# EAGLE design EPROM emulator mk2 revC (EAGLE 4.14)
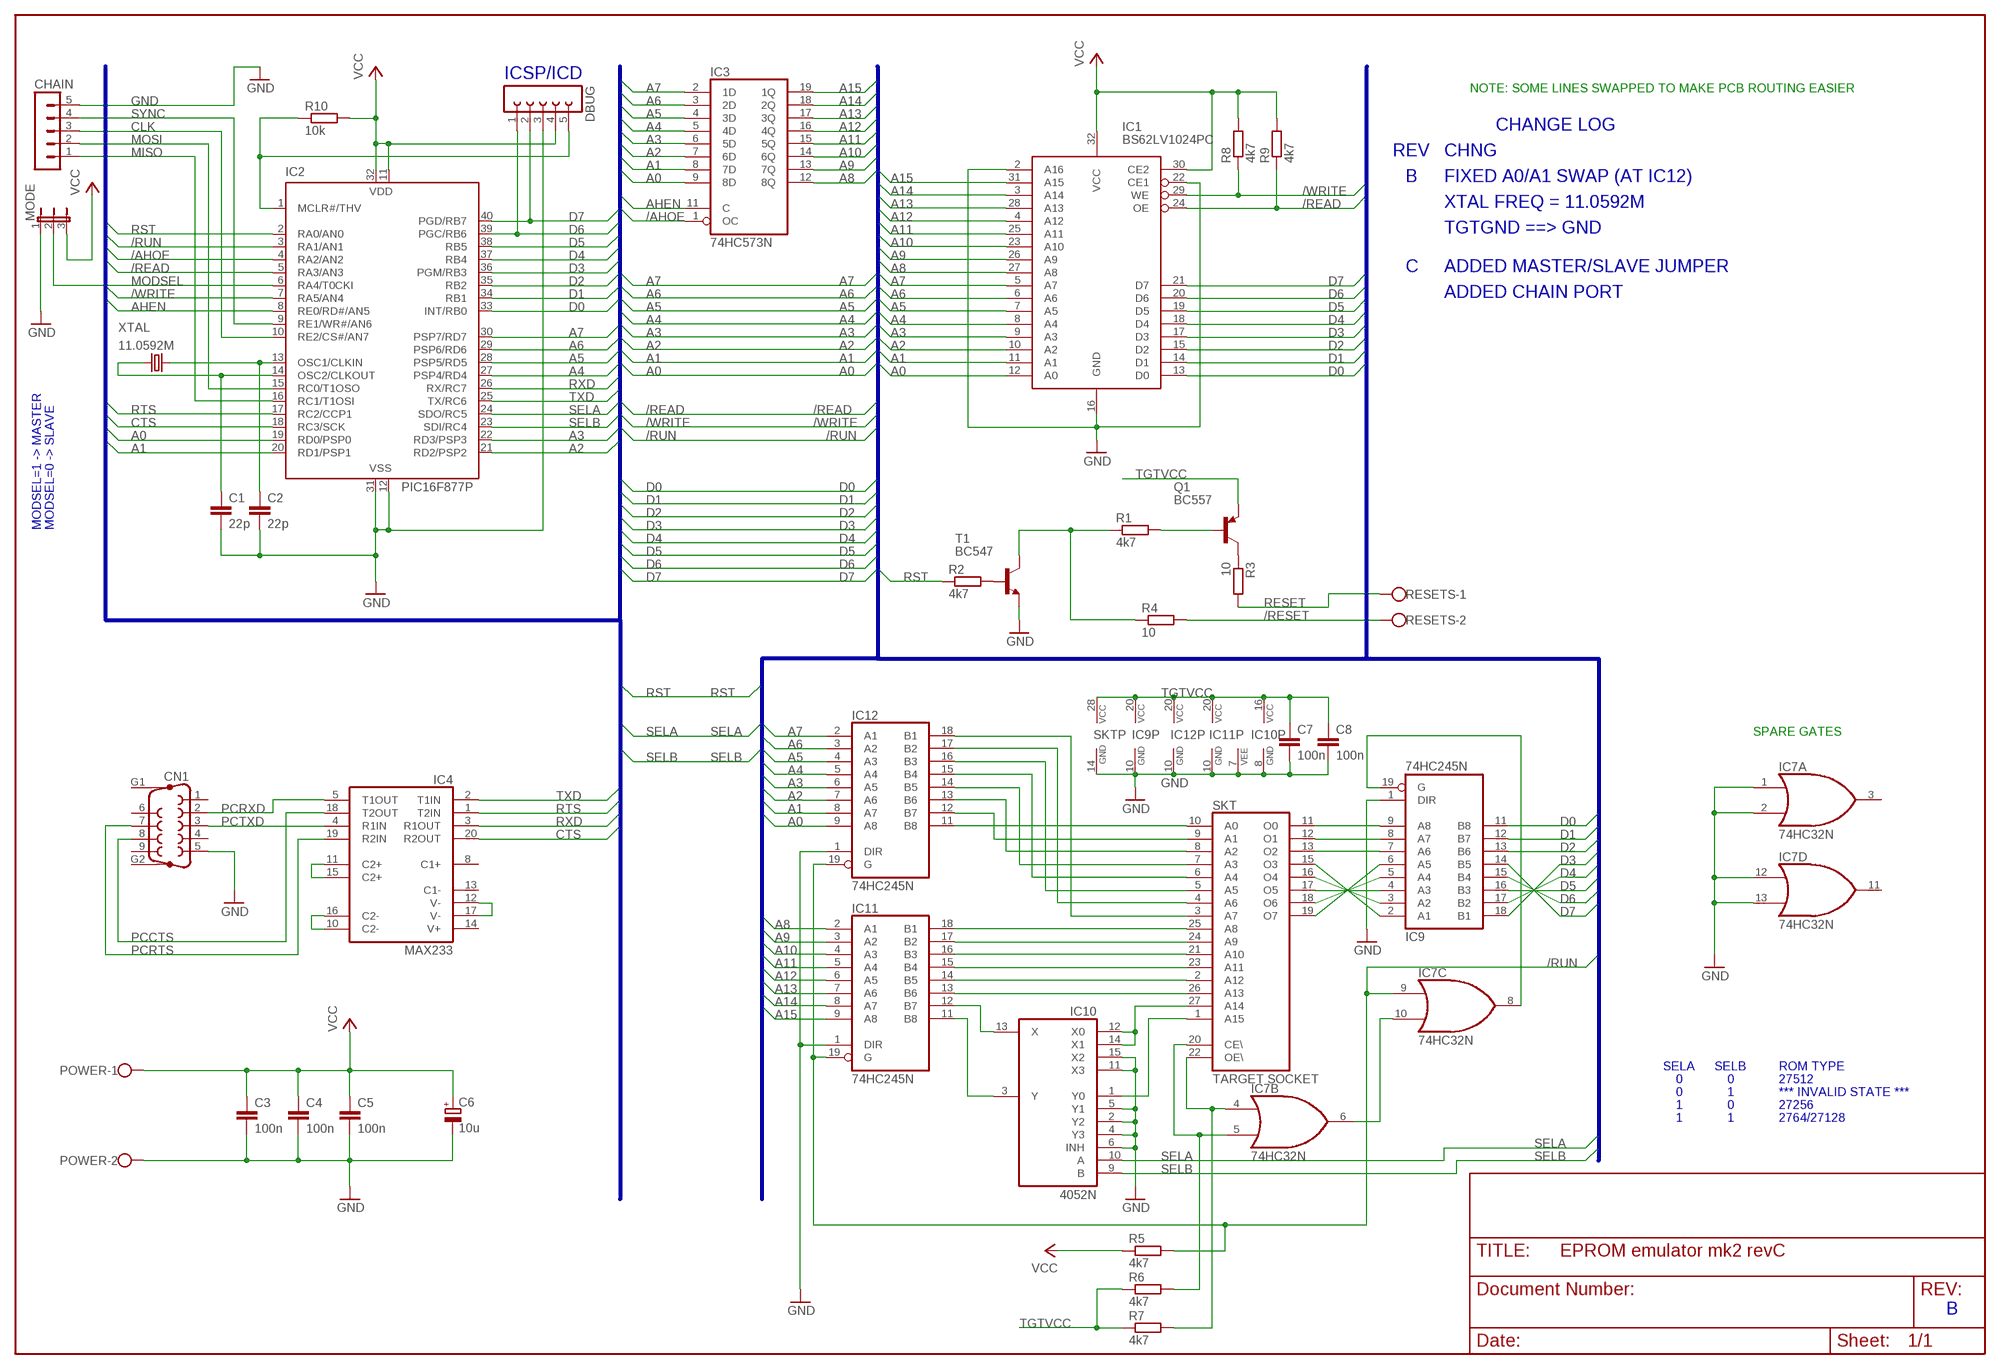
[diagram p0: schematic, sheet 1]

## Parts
C1  22p  C-EU025-024X044  [C025-024X044]
C2  22p  C-EU025-024X044  [C025-024X044]
C3  100n  C-EU050-025X075  [C050-025X075]
C4  100n  C-EU050-025X075  [C050-025X075]
C5  100n  C-EU050-025X075  [C050-025X075]
C6  10u  CPOL-EUE2.5-5  [E2,5-5]
C7  100n  C-EU050-025X075  [C050-025X075]
C8  100n  C-EU050-025X075  [C050-025X075]
CHAIN  MA05-1  [MA05-1]
CN1  F09HP  [F09HP]
DBUG  FE05-1  [FE05-1]
IC1  BS62LV1024PC  [DIL32]
IC2  PIC16F877P  [DIL40]
IC3  74HC573N  [DIL20]
IC4  MAX233  [DIL20]
IC7  74HC32N  74LS32N  [DIL14]
IC9  74HC245N  74HCT245N  [DIL20]
IC10  4052N  [DIL16]
IC11  74HC245N  74HCT245N  [DIL20]
IC12  74HC245N  74HCT245N  [DIL20]
MODE  JP2E  [JP2]
POWER  W237-02P  [W237-132]
Q1  BC557  [TO92]
R1  4k7  R-EU_0207/10  [0207/10]
R2  4k7  R-EU_0207/10  [0207/10]
R3  10  R-EU_0207/10  [0207/10]
R4  10  R-EU_0207/10  [0207/10]
R5  4k7  R-EU_0207/10  [0207/10]
R6  4k7  R-EU_0207/10  [0207/10]
R7  4k7  R-EU_0207/10  [0207/10]
R8  4k7  R-EU_0207/10  [0207/10]
R9  4k7  R-EU_0207/10  [0207/10]
R10  10k  R-EU_0207/10  [0207/10]
RESETS  W237-102  [W237-102]
SKT  TARGET SOCKET  27512  [DIL28]
T1  BC547  [TO92]
XTAL  11.0592M  CRYTALHC49U-V  [HC49U-V]

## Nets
/AHOE: IC2.4(RA2/AN2) IC3.1(OC)
/READ: IC1.24(OE) IC2.5(RA3/AN3) R9.1
/RESET: R4.2 RESETS.2
/RUN: IC2.3(RA1/AN1) IC7.9(C:I0) IC11.19(G) IC12.19(G) R5.2
/WRITE: IC1.29(WE) IC2.7(RA5/AN4) R8.1
A0: IC1.12(A0) IC2.19(RD0/PSP0) IC3.9(8D) IC12.9(A8)
A1: IC1.11(A1) IC2.20(RD1/PSP1) IC3.8(7D) IC12.8(A7)
A2: IC1.10(A2) IC2.21(RD2/PSP2) IC3.7(6D) IC12.7(A6)
A3: IC1.9(A3) IC2.22(RD3/PSP3) IC3.6(5D) IC12.6(A5)
A4: IC1.8(A4) IC2.27(PSP4/RD4) IC3.5(4D) IC12.5(A4)
A5: IC1.7(A5) IC2.28(PSP5/RD5) IC3.4(3D) IC12.4(A3)
A6: IC1.6(A6) IC2.29(PSP6/RD6) IC3.3(2D) IC12.3(A2)
A7: IC1.5(A7) IC2.30(PSP7/RD7) IC3.2(1D) IC12.2(A1)
A8: IC1.27(A8) IC3.12(8Q) IC11.2(A1)
A9: IC1.26(A9) IC3.13(7Q) IC11.3(A2)
A10: IC1.23(A10) IC3.14(6Q) IC11.4(A3)
A11: IC1.25(A11) IC3.15(5Q) IC11.5(A4)
A12: IC1.4(A12) IC3.16(4Q) IC11.6(A5)
A13: IC1.28(A13) IC3.17(3Q) IC11.7(A6)
A14: IC1.3(A14) IC3.18(2Q) IC11.8(A7)
A15: IC1.31(A15) IC3.19(1Q) IC11.9(A8)
AHEN: IC2.8(RE0/RD#/AN5) IC3.11(C)
CLK: CHAIN.3 IC2.10(RE2/CS#/AN7)
CTS: IC2.18(RC3/SCK) IC4.20(R2OUT)
D0: IC1.13(D0) IC2.33(INT/RB0) IC9.11(B8)
D1: IC1.14(D1) IC2.34(RB1) IC9.12(B7)
D2: IC1.15(D2) IC2.35(RB2) IC9.13(B6)
D3: IC1.17(D3) IC2.36(PGM/RB3) IC9.18(B1)
D4: IC1.18(D4) IC2.37(RB4) IC9.17(B2)
D5: IC1.19(D5) IC2.38(RB5) IC9.16(B3)
D6: DBUG.1 IC1.20(D6) IC2.39(PGC/RB6) IC9.15(B4)
D7: DBUG.2 IC1.21(D7) IC2.40(PGD/RB7) IC9.14(B5)
GND: C1.2 C2.2 C3.2 C4.2 C5.2 C6.- C7.2 C8.2 CHAIN.5 CN1.5 DBUG.3 IC1.2(A16) IC1.16(GND) IC1.22(CE1) IC2.12(VSS) IC2.31(VSS) IC7.1(A:I0) IC7.2(A:I1) IC7.12(D:I0) IC7.13(D:I1) IC9.1(DIR) IC9.10(GND) IC10.2(Y2) IC10.4(Y3) IC10.5(Y1) IC10.6(INH) IC10.7(VEE) IC10.8(GND) IC10.11(X3) IC10.15(X2) IC11.1(DIR) IC11.10(GND) IC12.1(DIR) IC12.10(GND) MODE.1 POWER.2 SKT.14(GND) T1.1(E)
MISO: CHAIN.1 IC2.16(RC1/T1OSI)
MODSEL: IC2.6(RA4/T0CKI) MODE.2
MOSI: CHAIN.2 IC2.15(RC0/T1OSO)
N$1: C2.1 IC2.13(OSC1/CLKIN) XTAL.2
N$2: C1.1 IC2.14(OSC2/CLKOUT) XTAL.1
N$3: DBUG.5 IC2.1(MCLR#/THV) R10.1
N$4: IC9.6(A5) SKT.19(O7)
N$5: IC4.12(V-) IC4.17(V-)
N$6: IC4.10(C2-) IC4.16(C2-)
N$7: IC4.11(C2+) IC4.15(C2+)
N$8: IC9.5(A4) SKT.18(O6)
N$9: IC9.4(A3) SKT.17(O5)
N$10: IC9.3(A2) SKT.16(O4)
N$11: IC9.2(A1) SKT.15(O3)
N$12: IC12.11(B8) SKT.10(A0)
N$13: IC12.12(B7) SKT.9(A1)
N$14: IC12.13(B6) SKT.8(A2)
N$15: IC12.14(B5) SKT.7(A3)
N$16: IC12.15(B4) SKT.6(A4)
N$17: IC9.9(A8) SKT.11(O0)
N$18: IC9.8(A7) SKT.12(O1)
N$19: IC12.16(B3) SKT.5(A5)
N$20: IC9.7(A6) SKT.13(O2)
N$21: IC12.17(B2) SKT.4(A6)
N$22: IC12.18(B1) SKT.3(A7)
N$23: Q1.3(C) R3.1
N$25: R2.2 T1.2(B)
N$26: IC7.5(B:I1) R6.2 SKT.20(CE\)
N$27: IC7.4(B:I0) R7.2 SKT.22(OE\)
N$28: IC7.8(C:O) IC9.19(G)
N$29: IC7.6(B:O) IC7.10(C:I1)
N$30: IC10.12(X0) IC10.14(X1) SKT.27(A14)
N$31: IC10.1(Y0) SKT.1(A15)
N$32: IC11.13(B6) SKT.26(A13)
N$33: IC10.13(X) IC11.12(B7)
N$34: IC10.3(Y) IC11.11(B8)
N$35: IC11.14(B5) SKT.2(A12)
N$36: IC11.15(B4) SKT.23(A11)
N$37: IC11.16(B3) SKT.21(A10)
N$38: IC11.17(B2) SKT.24(A9)
N$39: IC11.18(B1) SKT.25(A8)
N$40: Q1.2(B) R1.2
N$41: R1.1 R4.1 T1.3(C)
PCCTS: CN1.8 IC4.18(T2OUT)
PCRTS: CN1.7 IC4.19(R2IN)
PCRXD: CN1.2 IC4.5(T1OUT)
PCTXD: CN1.3 IC4.4(R1IN)
RESET: R3.2 RESETS.1
RST: IC2.2(RA0/AN0) R2.1
RTS: IC2.17(RC2/CCP1) IC4.1(T2IN)
RXD: IC2.26(RX/RC7) IC4.3(R1OUT)
SELA: IC2.24(SDO/RC5) IC10.10(A)
SELB: IC2.23(SDI/RC4) IC10.9(B)
SYNC: CHAIN.4 IC2.9(RE1/WR#/AN6)
TGTVCC: C7.1 C8.1 IC9.20(VCC) IC10.16(VCC) IC11.20(VCC) IC12.20(VCC) Q1.1(E) R6.1 R7.1 SKT.28(VCC)
TXD: IC2.25(TX/RC6) IC4.2(T1IN)
VCC: C3.1 C4.1 C5.1 C6.+ DBUG.4 IC1.30(CE2) IC1.32(VCC) IC2.11(VDD) IC2.32(VDD) MODE.3 POWER.1 R5.1 R8.2 R9.2 R10.2
Unconnected: CN1.1 CN1.4 CN1.6 CN1.9 CN1.G1 CN1.G2 IC4.8(C1+) IC4.13(C1-) IC4.14(V+) IC7.3(A:O) IC7.11(D:O)

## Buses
A[0..15],D[0..7],/WRITE,/READ,/RUN,SELA,SELB,RST
D[0..7],A[0..7],RXD,TXD,RTS,CTS,/WRITE,/READ,/RUN,SELA,SELB,AHEN,/AHOE,RST

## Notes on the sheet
- ICSP/ICD
- NOTE: SOME LINES SWAPPED TO MAKE PCB ROUTING EASIER
- CHANGE LOG
- REV | CHNG
- B | FIXED A0/A1 SWAP (AT IC12)
- XTAL FREQ = 11.0592M
- TGTGND ==> GND
- C | ADDED MASTER/SLAVE JUMPER
- ADDED CHAIN PORT
- MODSEL=1 -> MASTER | MODSEL=0 -> SLAVE
- SPARE GATES
- SELA | SELB | ROM TYPE
- 0 | 0 | 27512
- 0 | 1 | *** INVALID STATE ***
- 1 | 0 | 27256
- 1 | 1 | 2764/27128
- B

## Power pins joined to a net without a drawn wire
GND: IC3.10(GND) IC4.6(GND) IC4.9(GND) IC7.7(P:GND)
VCC: IC3.20(VCC) IC4.7(VCC) IC7.14(P:VCC)

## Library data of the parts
C1-C5 C7 C8 = rcl:C-EU: CAPACITOR, European symbol
C6 = rcl:CPOL-EU: POLARIZED CAPACITOR, European symbol
CHAIN = con-lstb:MA05-1: PIN HEADER
CN1 = con-subd:F09HP: SUB-D
DBUG = con-lsta:FE05-1: FEMALE HEADER
IC1 = brilliance sram:BS62LV1024
IC2 = microchip:PIC16F87*: MICROCONTROLLER
IC3 = 74xx-us:74*573: 8-bit D latch BUS DRIVER
IC4 = maxim:MAX233: RS232 TRANSEIVER
IC7 = 74xx-us:74*32: Quad 2-input OR gate
IC9 IC11 IC12 = 74xx-eu:74*245: Octal BUS TRANSCEIVER, 3-state
IC10 = 40xx:4052: Dual 4-channel ANALOG MULTIPLEXER
MODE = jumper:JP2E: JUMPER
POWER = con-wago-508:W237-02P: WAGO SREW CLAMP
Q1 = transistor-pnp:BC557: PNP Transistor
R1-R10 = rcl:R-EU_: RESISTOR, European symbol
RESETS = con-wago-500:W237-102: WAGO SCREW CLAMP
SKT = memory:27512: MEMORY
T1 = transistor:BC547: NPN TRANSISTOR
XTAL = crystal:CRYTAL: CRYSTAL

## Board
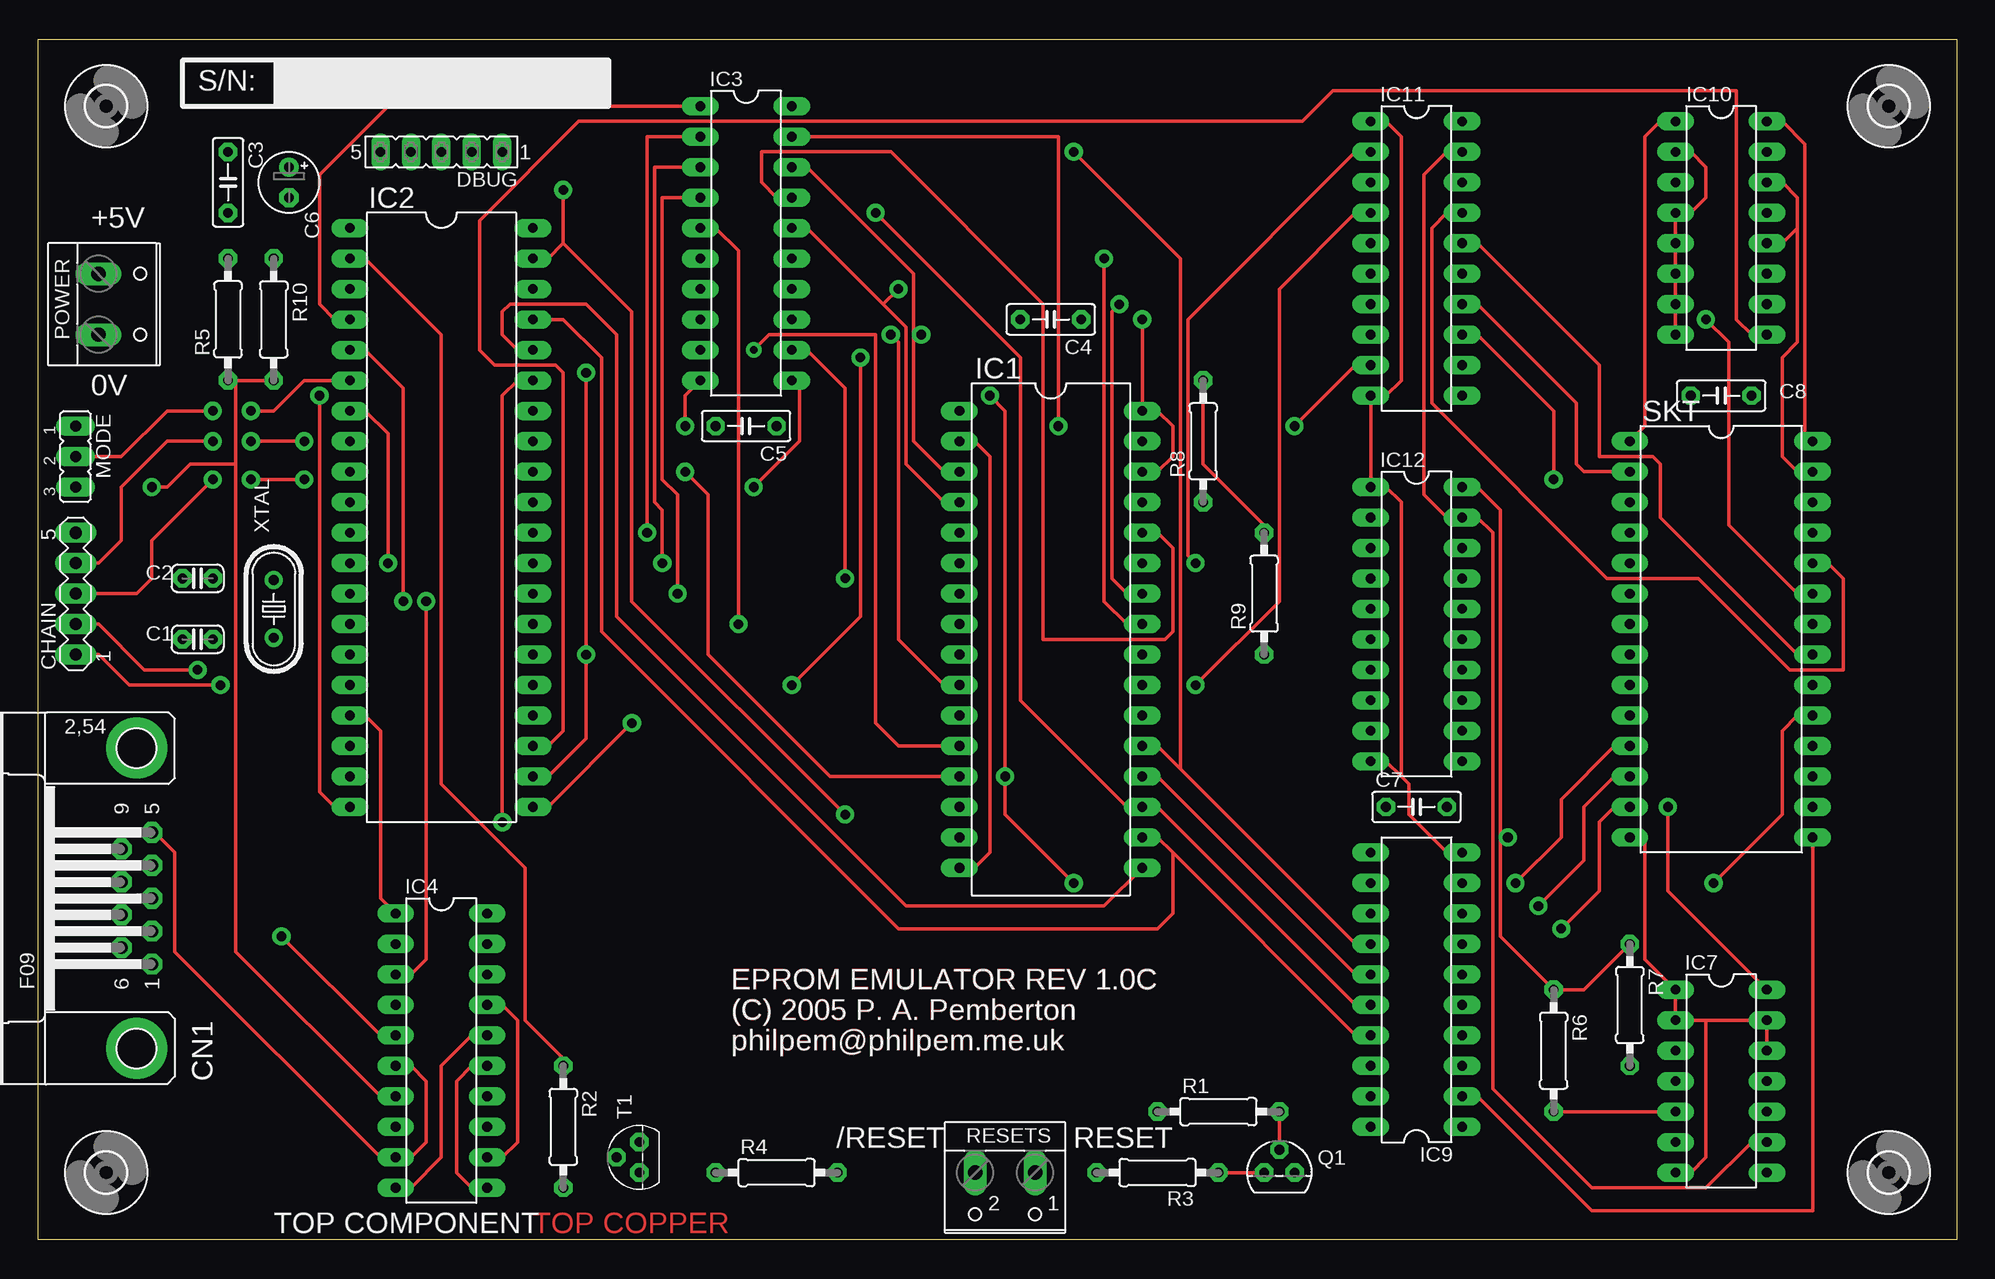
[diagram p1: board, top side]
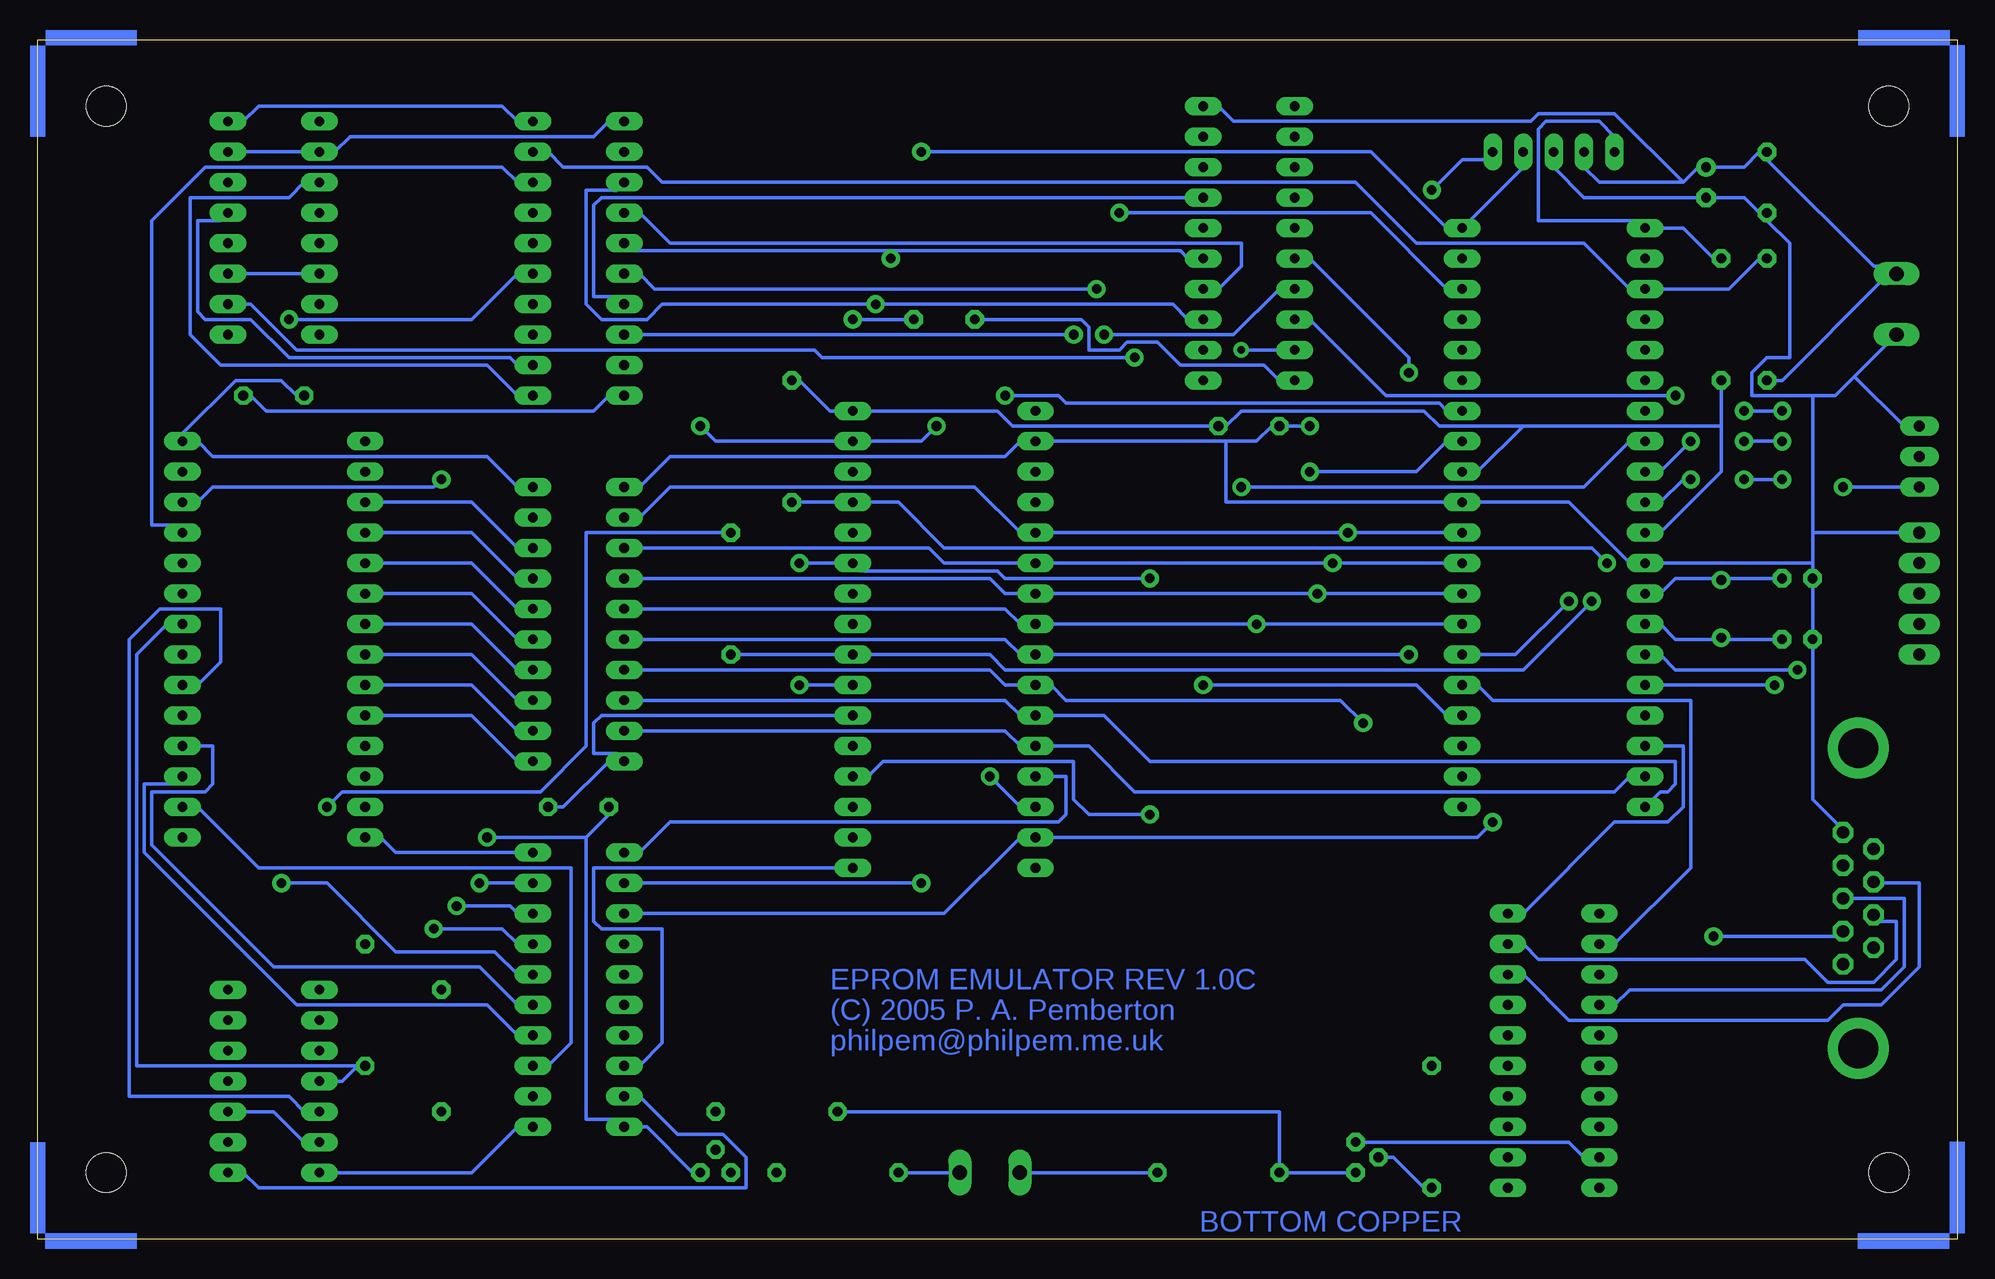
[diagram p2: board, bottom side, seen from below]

Size 160 x 100 mm. Coordinates in mm from the lower left corner, seen from the top.
Outline: 0,0 160,0 160,100 0,100 0,0
Copper layers (1*16): Top 0.035mm / dielectric 1.5mm / Bottom 0.035mm
Design rules "basic_philpem": minimum track width 12mil, minimum drill 0.8mm, track to track 12mil, track to pad 12mil, pad to pad 12mil, via to via 12mil, smd to smd 10mil, copper to edge 40mil, drill to drill 10mil, minimum pad ring 14mil, minimum via ring 14mil, stop-mask expansion 0mil, vias tented up to drill 0mil, thermal gap 10mil
tRestrict: area 80.6,75.4 to 83.2,77.9; area 85.7,75.4 to 88.3,77.9; area 111.1,34.8 to 113.7,37.3; area 116.2,34.8 to 118.7,37.3; area 136.5,69 to 139.1,71.6; area 141.6,69 to 144.1,71.6; area 55.2,66.5 to 57.8,69; area 60.3,66.5 to 62.9,69; area 10.8,53.8 to 15.9,56.3; area 10.8,48.7 to 15.9,51.3; area 3.2,79.2 to 7,81.8; area 3.2,74.1 to 7,76.7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

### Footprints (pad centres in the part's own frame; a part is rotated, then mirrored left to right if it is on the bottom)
C025-024X044 = drill 0.813 octagon: 1 -1.27,0; 2 1.27,0
C050-025X075 = drill 0.813 octagon: 1 -2.54,0; 2 2.54,0
E2,5-5 = drill 0.813 pad 1.6 round: + -1.27,0 | drill 0.813 pad 1.6 octagon: - 1.27,0
MA05-1 = drill 1.016 long: 1 -5.08,0; 2 -2.54,0; 3 0,0; 4 2.54,0; 5 5.08,0
F09HP = drill 1.016 octagon: 1 -5.486,-1.27; 2 -2.743,-1.27; 3 0,-1.27; 4 2.743,-1.27; 5 5.486,-1.27; 6 -4.115,1.27; 7 -1.372,1.27; 8 1.372,1.27; 9 4.115,1.27 | drill 3.302 pad 5.08 round: G1 -12.522,0; G2 12.522,0
FE05-1 = drill 0.813 long: 1 -5.08,0; 2 -2.54,0; 3 0,0; 4 2.54,0; 5 5.08,0
DIL32 = drill 0.813 long: 1 -19.05,-7.62; 2 -16.51,-7.62; 3 -13.97,-7.62; 4 -11.43,-7.62; 5 -8.89,-7.62; 6 -6.35,-7.62; 7 -3.81,-7.62; 8 -1.27,-7.62; 9 1.27,-7.62; 10 3.81,-7.62; 11 6.35,-7.62; 12 8.89,-7.62; 13 11.43,-7.62; 14 13.97,-7.62; 15 16.51,-7.62; 16 19.05,-7.62; 17 19.05,7.62; 18 16.51,7.62; 19 13.97,7.62; 20 11.43,7.62; 21 8.89,7.62; 22 6.35,7.62; 23 3.81,7.62; 24 1.27,7.62; 25 -1.27,7.62; 26 -3.81,7.62; 27 -6.35,7.62; 28 -8.89,7.62; 29 -11.43,7.62; 30 -13.97,7.62; 31 -16.51,7.62; 32 -19.05,7.62
DIL40 = drill 0.813 long: 1 -24.13,-7.62; 2 -21.59,-7.62; 3 -19.05,-7.62; 4 -16.51,-7.62; 5 -13.97,-7.62; 6 -11.43,-7.62; 7 -8.89,-7.62; 8 -6.35,-7.62; 9 -3.81,-7.62; 10 -1.27,-7.62; 11 1.27,-7.62; 12 3.81,-7.62; 13 6.35,-7.62; 14 8.89,-7.62; 15 11.43,-7.62; 16 13.97,-7.62; 17 16.51,-7.62; 18 19.05,-7.62; 19 21.59,-7.62; 20 24.13,-7.62; 21 24.13,7.62; 22 21.59,7.62; 23 19.05,7.62; 24 16.51,7.62; 25 13.97,7.62; 26 11.43,7.62; 27 8.89,7.62; 28 6.35,7.62; 29 3.81,7.62; 30 1.27,7.62; 31 -1.27,7.62; 32 -3.81,7.62; 33 -6.35,7.62; 34 -8.89,7.62; 35 -11.43,7.62; 36 -13.97,7.62; 37 -16.51,7.62; 38 -19.05,7.62; 39 -21.59,7.62; 40 -24.13,7.62
DIL20 = drill 0.813 long: 1 -11.43,-3.81; 2 -8.89,-3.81; 3 -6.35,-3.81; 4 -3.81,-3.81; 5 -1.27,-3.81; 6 1.27,-3.81; 7 3.81,-3.81; 8 6.35,-3.81; 9 8.89,-3.81; 10 11.43,-3.81; 11 11.43,3.81; 12 8.89,3.81; 13 6.35,3.81; 14 3.81,3.81; 15 1.27,3.81; 16 -1.27,3.81; 17 -3.81,3.81; 18 -6.35,3.81; 19 -8.89,3.81; 20 -11.43,3.81
DIL14 = drill 0.813 long: 1 -7.62,-3.81; 2 -5.08,-3.81; 3 -2.54,-3.81; 4 0,-3.81; 5 2.54,-3.81; 6 5.08,-3.81; 7 7.62,-3.81; 8 7.62,3.81; 9 5.08,3.81; 10 2.54,3.81; 11 0,3.81; 12 -2.54,3.81; 13 -5.08,3.81; 14 -7.62,3.81
DIL16 = drill 0.813 long: 1 -8.89,-3.81; 2 -6.35,-3.81; 3 -3.81,-3.81; 4 -1.27,-3.81; 5 1.27,-3.81; 6 3.81,-3.81; 7 6.35,-3.81; 8 8.89,-3.81; 9 8.89,3.81; 10 6.35,3.81; 11 3.81,3.81; 12 1.27,3.81; 13 -1.27,3.81; 14 -3.81,3.81; 15 -6.35,3.81; 16 -8.89,3.81
JP2 = drill 0.914 long: 1 -2.54,0; 2 0,0; 3 2.54,0
W237-132 = drill 1.194 long: 1 -2.54,-0.635; 2 2.54,-0.635
TO92 = drill 0.813 octagon: 1 1.27,0; 2 0,1.905; 3 -1.27,0
0207/10 = drill 0.813 octagon: 1 -5.08,0; 2 5.08,0
W237-102 = drill 1.194 long: 1 -2.5,-1.27; 2 2.5,-1.27
DIL28 = drill 0.813 long: 1 -16.51,-7.62; 2 -13.97,-7.62; 3 -11.43,-7.62; 4 -8.89,-7.62; 5 -6.35,-7.62; 6 -3.81,-7.62; 7 -1.27,-7.62; 8 1.27,-7.62; 9 3.81,-7.62; 10 6.35,-7.62; 11 8.89,-7.62; 12 11.43,-7.62; 13 13.97,-7.62; 14 16.51,-7.62; 15 16.51,7.62; 16 13.97,7.62; 17 11.43,7.62; 18 8.89,7.62; 19 6.35,7.62; 20 3.81,7.62; 21 1.27,7.62; 22 -1.27,7.62; 23 -3.81,7.62; 24 -6.35,7.62; 25 -8.89,7.62; 26 -11.43,7.62; 27 -13.97,7.62; 28 -16.51,7.62
3,3 = hole 3.3: 0,0
HC49U-V = drill 0.813 round: 1 -2.413,0; 2 2.413,0

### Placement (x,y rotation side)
C1  13.33,50 180 top
C2  13.33,55.08 180 top
C3  15.87,88.1 270 top
C4  84.45,76.67 180 top
C5  59.05,67.78 180 top
C6  20.95,88.1 270 top
C7  114.93,36.03 0 top
C8  140.33,70.32 0 top
CHAIN  3.17,53.81 90 top
CN1  8.25,28.41 90 top
DBUG  33.65,90.64 180 top
IC1  84.45,50 270 top
IC2  33.65,60.16 270 top
IC3  59.05,83.02 270 top
IC4  33.65,15.71 270 top
IC7  140.33,13.17 270 top
IC9  114.93,20.79 90 top
IC10  140.33,84.29 270 top
IC11  114.93,81.75 270 top
IC12  114.93,51.27 270 top
MODE  3.17,65.24 270 top
POWER  5.71,77.94 270 top
Q1  103.5,5.55 0 top
R1  98.42,10.63 0 top
R2  43.81,9.36 270 top
R3  93.34,5.55 180 top
R4  61.59,5.55 0 top
R5  15.87,76.67 90 top
R6  126.36,15.71 270 top
R7  132.71,19.52 270 top
R8  97.15,66.51 90 top
R9  102.23,53.81 90 top
R10  19.68,76.67 270 top
RESETS  80.64,4.28 180 top
SKT  140.33,50 270 top
T1  50.16,6.82 90 top
U$1  [3,3]  5.71,94.45 0 top
U$2  [3,3]  5.71,5.55 0 top
U$3  [ANGLE-ARROW-NW1]  0.63,99.53 0 top
U$4  [ANGLE-ARROW-SE1]  159.38,0.47 0 top
U$5  [ANGLE-ARROW-SW1]  0.63,0.47 0 top
U$6  [ANGLE-NE1]  159.38,99.53 0 top
U$7  [3,3]  154.3,5.55 0 top
U$10  [3,3]  154.3,94.45 0 top
XTAL  19.68,52.54 90 top

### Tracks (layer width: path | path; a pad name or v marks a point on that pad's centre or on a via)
/AHOE
  Top 0.305: IC2.4 24.76,76.67 23.49,77.94 23.49,88.73 29.2,94.45 IC3.1
/READ  (via drill 0.8)
  Top 0.305: v30.47,53.17 30.47,70.95 27.3,74.13 IC2.5
  Bottom 0.305: R9.1 IC1.24 80.64,48.73 79.37,47.46 36.19,47.46 v30.47,53.17
/RESET
  Bottom 0.305: R4.2 RESETS.2
/RUN
  Top 0.305: IC11.19 117.47,90.64 115.56,88.73 115.56,62.06 117.47,60.16 IC12.19 120.01,60.16 121.28,58.89 121.28,12.54 129.53,4.28 139.06,4.28 142.87,8.09 IC7.9
  Bottom 0.305: R5.2 16.5,81.75 19.04,79.21 IC2.3 27.3,79.21 31.11,83.02 45.08,83.02 50.16,88.1 107.94,88.1 109.21,89.37 116.2,89.37 117.47,90.64 IC11.19
/WRITE  (via drill 0.8)
  Top 0.305: v29.2,56.35 29.2,67.14 27.3,69.05 IC2.7
  Bottom 0.305: R8.1 IC1.29 88.26,61.43 84.45,57.62 30.47,57.62 v29.2,56.35
A0  (via drill 0.6)
  Top 0.305: v59.69,74.13 60.96,75.4 69.84,75.4 69.84,43.02 71.75,41.11 IC1.12
  Bottom 0.305: IC2.19 27.3,38.57 28.57,37.3 68.57,37.3 72.38,41.11 IC1.12 78.1,41.11 79.37,42.38 IC12.9 | v59.69,74.13 IC3.9
A1  (via drill 0.8)
  Top 0.305: v23.49,70.32 23.49,37.3 24.76,36.03 IC2.20
  Bottom 0.305: IC2.20 24.76,37.3 24.12,37.3 23.49,37.94 23.49,39.84 67.3,39.84 71.11,43.65 IC1.11 78.1,43.65 79.37,44.92 IC12.8 | v23.49,70.32 47.62,70.32 53.97,76.67 IC3.8
A2  (via drill 0.8)
  Top 0.305: v49.53,43.02 42.54,36.03 IC2.21 | v71.11,75.4 71.75,74.77 71.75,50 75.56,46.19 IC1.10
  Bottom 0.305: v49.53,43.02 51.43,44.92 74.29,44.92 75.56,46.19 IC1.10 79.37,46.19 80.64,47.46 IC12.7 | v71.11,75.4 60.32,75.4 56.51,79.21 IC3.7
A3  (via drill 0.8)
  Top 0.305: IC2.22 42.54,38.57 45.72,41.74 v45.72,48.73 v45.72,72.22
  Bottom 0.305: v45.72,48.73 IC1.9 78.1,48.73 79.37,50 IC12.6 | v45.72,72.22 45.72,73.5 53.97,81.75 IC3.6
A4  (via drill 0.8)
  Top 0.305: v58.41,51.27 58.41,82.39 56.51,84.29 IC3.5
  Bottom 0.305: IC2.27 v58.41,51.27 IC1.8 78.1,51.27 79.37,52.54 IC12.5
A5  (via drill 0.8)
  Top 0.305: v53.34,53.81 53.34,62.06 52.07,63.34 52.07,86.83 IC3.4
  Bottom 0.305: IC2.28 v53.34,53.81 IC1.7 79.37,53.81 80.64,55.08 IC12.4
A6  (via drill 0.8)
  Top 0.305: v52.07,56.35 52.07,60.8 51.43,61.43 51.43,89.37 IC3.3
  Bottom 0.305: IC2.29 v52.07,56.35 IC1.6 84.45,56.35 85.72,57.62 IC12.3
A7  (via drill 0.8)
  Top 0.305: v50.8,58.89 50.8,91.91 IC3.2
  Bottom 0.305: IC2.30 v50.8,58.89 IC1.5 78.1,58.89 81.91,62.7 107.31,62.7 109.85,60.16 IC12.2
A8  (via drill 0.8)
  Top 0.305: v67.3,55.08 67.3,70.95 64.13,74.13 IC3.12 | v96.52,56.35 95.88,56.98 95.88,76.67 109.85,90.64 IC11.2
  Bottom 0.305: v67.3,55.08 79.37,55.08 80,55.71 91.44,55.71 IC1.27 v96.52,56.35
A9  (via drill 0.8)
  Top 0.305: v90.16,77.94 89.53,77.3 89.53,55.08 90.8,53.81 IC1.26
  Bottom 0.305: IC3.13 64.13,76.67 65.4,77.94 v90.16,77.94 107.94,77.94 109.21,76.67 113.02,76.67 114.3,77.94 114.3,87.47 111.75,87.47 IC11.3
A10  (via drill 0.8)
  Top 0.305: v96.52,46.19 103.5,53.17 103.5,79.21 109.85,85.56 IC11.4
  Bottom 0.305: IC1.23 v96.52,46.19 | IC3.14 61.59,79.21 59.69,81.11 59.69,83.02 107.31,83.02 109.85,85.56 IC11.4
A11  (via drill 0.8)
  Top 0.305: v88.89,81.75 88.89,53.17 90.8,51.27 IC1.25
  Bottom 0.305: 88.89,82.39 110.48,82.39 IC11.5 | 88.89,82.39 64.77,82.39 64.13,81.75 IC3.15 | v88.89,81.75 88.89,82.39
A12  (via drill 0.8)
  Top 0.305: 70.48,77.94 64.13,84.29 IC3.16 | 70.48,77.94 72.38,76.03 72.38,64.61 75.56,61.43 IC1.4 | 70.48,77.94 v71.75,79.21
  Bottom 0.305: v71.75,79.21 108.58,79.21 109.85,80.48 IC11.6
A13
  Top 0.305: IC1.28 93.34,58.89 94.61,57.62 94.61,50.63 93.97,50 83.81,50 83.81,77.94 71.11,90.64 60.32,90.64 60.32,88.1 61.59,86.83 IC3.17
  Bottom 0.305: IC3.17 113.02,86.83 113.66,86.19 113.66,78.58 111.75,78.58 IC11.7
A14  (via drill 0.8)
  Top 0.305: 73.02,75.4 73.02,80.48 64.13,89.37 IC3.18 | 73.02,75.4 73.02,66.51 75.56,63.97 IC1.3 | 73.02,75.4 v73.66,75.4
  Bottom 0.305: v73.66,75.4 IC11.8
A15  (via drill 0.8)
  Top 0.305: v85.08,67.78 85.08,91.91 IC3.19 | v104.77,67.78 109.85,72.86 IC11.9
  Bottom 0.305: v85.08,67.78 86.35,66.51 IC1.31 103.5,66.51 v104.77,67.78
AHEN  (via drill 0.8)
  Top 0.305: v59.69,62.7 63.5,66.51 63.5,70.95 IC3.11
  Bottom 0.305: v59.69,62.7 31.11,62.7 27.3,66.51 IC2.8
CLK  (via drill 0.8)
  Top 0.305: v17.77,63.34 v22.22,63.34 | v14.6,63.34 9.52,58.25 9.52,55.08 8.25,53.81 CHAIN.3
  Bottom 0.305: v22.22,63.34 22.86,63.34 24.76,61.43 IC2.10 | v14.6,63.34 v17.77,63.34
CTS
  Bottom 0.305: IC4.20 36.19,27.14 28.57,34.76 24.12,34.76 22.86,36.03 22.86,41.11 IC2.18
D0  (via drill 0.8)
  Top 0.305: v53.97,63.97 55.88,62.06 55.88,48.73 66.03,38.57 IC1.13
  Bottom 0.305: v53.97,63.97 45.08,63.97 42.54,66.51 IC2.33 | IC9.11 109.85,32.22 107.31,34.76 74.92,34.76 74.29,35.39 74.29,38.57 IC1.13
D1  (via drill 0.8)
  Top 0.305: v79.37,70.32 80.64,69.05 v80.64,38.57 80.64,35.39 v86.35,29.68
  Bottom 0.305: v79.37,70.32 74.92,70.32 74.29,69.69 43.18,69.69 42.54,69.05 IC2.34 | v80.64,38.57 78.1,36.03 IC1.14 | v86.35,29.68 IC9.12
D2  (via drill 0.8)
  Top 0.305: v38.73,34.76 38.73,70.32 40,71.59 IC2.35
  Bottom 0.305: IC9.13 84.45,27.14 78.1,33.49 IC1.15 40,33.49 v38.73,34.76
D3
  Top 0.305: IC1.17 88.89,27.77 72.38,27.77 48.26,51.91 48.26,75.4 45.72,77.94 39.37,77.94 38.73,77.3 38.73,75.4 40,74.13 IC2.36
  Bottom 0.305: IC9.18 109.85,14.44 107.94,16.34 107.94,25.87 113.02,25.87 113.66,26.5 113.66,30.95 IC1.17
D4
  Top 0.305: 94.61,32.22 94.61,27.14 93.34,25.87 71.75,25.87 46.98,50.63 46.98,73.5 43.81,76.67 IC2.37 | 94.61,32.22 93.34,33.49 IC1.18 | 94.61,32.22 109.85,16.98 IC9.17
D5  (via drill 0.8)
  Top 0.305: v69.84,85.56 81.91,73.5 81.91,44.92 90.8,36.03 IC1.19 93.34,36.03 109.85,19.52 IC9.16
  Bottom 0.305: v69.84,85.56 48.89,85.56 42.54,79.21 IC2.38
D6  (via drill 0.8)
  Top 0.305: 43.81,83.02 42.54,81.75 IC2.39 | 43.81,83.02 v43.81,87.47 | IC9.15 109.85,22.06 93.34,38.57 IC1.20 | 43.81,83.02 49.53,77.3 49.53,53.17 v67.3,35.39
  Bottom 0.305: v43.81,87.47 41.27,90 39.37,90 DBUG.1 | v67.3,35.39 72.38,35.39 73.66,36.66 73.66,39.84 89.53,39.84 90.8,38.57 IC1.20
D7  (via drill 0.8)
  Top 0.305: 95.24,39.2 93.34,41.11 IC1.21 | 95.24,39.2 109.85,24.6 IC9.14 | v86.35,90.64 95.24,81.75 95.24,39.2
  Bottom 0.305: DBUG.2 36.19,89.37 IC2.40 42.54,84.29 48.89,90.64 v86.35,90.64
GND  (via drill 0.8)
  Top 0.305: IC10.8 IC10.7 IC10.6 IC10.5 IC10.4 137.79,85.56 139.06,86.83 139.06,89.37 137.79,90.64 IC10.2 | IC7.12 IC7.13 139.06,18.25 | 139.06,18.25 IC7.2 IC7.1 133.98,23.33 133.98,33.49 SKT.14 | 113.66,38.57 112.39,39.84 IC12.10 | 113.66,38.57 114.3,37.94 114.3,35.39 117.47,32.22 IC9.10 | 139.06,18.25 139.06,6.82 137.79,5.55 IC7.7 | 113.66,38.57 113.66,61.43 112.39,62.7 IC12.1 IC11.10 112.39,70.32 113.66,71.59 113.66,91.91 112.39,93.18 IC11.1 | v53.97,67.78 53.97,70.32 IC3.10 | IC1.16 78.1,30.95 79.37,32.22 79.37,65.24 78.1,66.51 IC1.2 | IC4.6 31.11,14.44 32.38,13.17 32.38,8.09 31.11,6.82 IC4.9 28.57,6.82 11.43,23.96 11.43,32.22 10.16,33.49 CN1.5
  Bottom 0.305: IC10.6 IC10.11 | IC11.1 112.39,93.18 113.66,91.91 133.98,91.91 135.25,90.64 IC10.2 IC10.15 | C8.2 142.23,70.32 140.97,69.05 113.66,69.05 112.39,70.32 IC11.10 | IC9.1 120.01,9.36 123.82,5.55 IC7.7 | C7.2 116.2,36.03 112.39,39.84 IC12.10 111.75,40.48 113.66,40.48 113.66,43.02 113.02,43.65 IC1.22 | SKT.14 131.44,33.49 130.17,32.22 IC9.10 | v53.97,67.78 C5.2 57.15,67.78 58.41,66.51 60.96,66.51 | C4.2 73.02,76.67 72.38,76.03 72.38,74.13 69.84,74.13 69.21,74.77 66.67,74.77 64.77,72.86 57.78,72.86 56.51,71.59 IC3.10 | 60.96,66.51 IC1.2 78.1,66.51 79.37,65.24 107.31,65.24 109.85,62.7 IC12.1 | T1.1 32.38,8.09 31.11,6.82 IC4.9 | DBUG.3 33.65,89.37 31.11,86.83 C6.- 17.77,86.83 16.5,85.56 C3.2 15.87,84.92 13.97,83.02 13.97,73.5 15.87,73.5 17.14,72.22 17.14,70.32 12.06,70.32 | C1.2 C2.2 | C1.2 12.06,36.66 9.52,34.12 CN1.5 | C1.2 C2.2 | C2.2 12.06,56.35 | 12.06,56.35 12.06,58.89 | 12.06,58.89 12.06,70.32 | 12.06,70.32 10.16,70.32 8.57,71.91 | 8.57,71.91 POWER.2 | 12.06,56.35 IC2.12 27.3,56.35 32.38,61.43 IC2.31 60.96,61.43 60.96,66.51 | 12.06,58.89 CHAIN.5 | 8.57,71.91 4.44,67.78 MODE.1
MISO  (via drill 0.8)
  Top 0.305: v15.24,46.19 7.62,46.19 5.08,48.73 CHAIN.1
  Bottom 0.305: v15.24,46.19 IC2.16
MODSEL  (via drill 0.8)
  Top 0.305: v14.6,69.05 10.79,69.05 6.98,65.24 MODE.2 | v17.77,69.05 19.68,69.05 22.22,71.59 IC2.6
  Bottom 0.305: v14.6,69.05 v17.77,69.05
MOSI  (via drill 0.8)
  Top 0.305: v13.33,47.46 8.89,47.46 5.08,51.27 CHAIN.2
  Bottom 0.305: v13.33,47.46 23.49,47.46 24.76,48.73 IC2.15
N$1
  Bottom 0.305: C2.1 19.04,55.08 XTAL.2 20.31,55.08 23.49,55.08 24.76,53.81 IC2.13
N$2
  Bottom 0.305: C1.1 19.04,50 XTAL.1 20.31,50 23.49,50 24.76,51.27 IC2.14
N$3
  Bottom 0.305: R10.1 20.31,81.75 22.86,84.29 IC2.1 26.66,84.92 34.92,84.92 34.92,92.55 34.29,93.18 29.84,93.18 28.57,91.91 DBUG.5
N$4  (via drill 0.8)
  Top 0.305: v139.69,29.68 145.41,35.39 145.41,42.38 146.68,43.65 SKT.19
  Bottom 0.305: v139.69,29.68 135.88,29.68 130.17,23.96 121.91,23.96 120.01,22.06 IC9.6
N$5
  Top 0.305: IC4.12 38.73,6.82 40,8.09 40,18.25 38.73,19.52 IC4.17
N$6
  Top 0.305: IC4.10 31.11,4.28 33.65,6.82 33.65,14.44 36.19,16.98 IC4.16
N$7
  Top 0.305: IC4.11 36.19,4.28 34.92,5.55 34.92,13.17 36.19,14.44 IC4.15
N$8
  Bottom 0.305: IC9.5 120.01,19.52 123.19,22.7 140.33,22.7 150.49,32.85 150.49,37.3 146.04,37.3 145.41,37.94 145.41,41.11 SKT.18
N$9
  Bottom 0.305: IC9.4 120.01,16.98 122.55,19.52 138.42,19.52 151.12,32.22 151.12,37.94 148.59,37.94 SKT.17
N$10
  Bottom 0.305: IC9.3 117.47,14.44 115.56,16.34 115.56,30.95 141.6,30.95 146.68,36.03 SKT.16
N$11
  Top 0.305: SKT.15 147.95,2.38 129.53,2.38 120.01,11.9 IC9.2
N$12
  Bottom 0.305: IC12.11 120.01,39.84 123.82,43.65 SKT.10
N$13
  Bottom 0.305: IC12.12 120.01,42.38 123.82,46.19 SKT.9
N$14
  Bottom 0.305: IC12.13 120.01,44.92 123.82,48.73 SKT.8
N$15
  Bottom 0.305: IC12.14 120.01,47.46 123.82,51.27 SKT.7
N$16
  Bottom 0.305: IC12.15 120.01,50 123.82,53.81 SKT.6
N$17  (via drill 0.8)
  Top 0.305: v123.19,29.68 126.99,33.49 126.99,36.66 131.44,41.11 SKT.11
  Bottom 0.305: IC9.9 v123.19,29.68
N$18  (via drill 0.8)
  Top 0.305: v125.09,27.77 128.9,31.58 128.9,36.03 131.44,38.57 SKT.12
  Bottom 0.305: v125.09,27.77 120.64,27.77 120.01,27.14 IC9.8
N$19
  Bottom 0.305: IC12.16 120.01,52.54 123.82,56.35 SKT.5
N$20  (via drill 0.8)
  Top 0.305: v126.99,25.87 130.17,29.04 130.17,34.76 131.44,36.03 SKT.13
  Bottom 0.305: v126.99,25.87 121.28,25.87 120.01,24.6 IC9.7
N$21
  Bottom 0.305: IC12.17 120.01,55.08 123.82,58.89 SKT.4
N$22
  Bottom 0.305: IC12.18 120.01,57.62 123.82,61.43 SKT.3
N$23
  Top 0.305: R3.1 Q1.3
N$25
  Bottom 0.305: R2.2 44.45,4.28 46.98,6.82 T1.2
N$26
  Top 0.305: R6.2 IC7.5
  Bottom 0.305: SKT.20 146.68,46.19 144.78,48.09 144.78,52.54 149.85,52.54 152.39,50 152.39,11.9 139.06,11.9 137.79,10.63 IC7.5
N$27
  Bottom 0.305: 133.34,14.44 134.62,13.17 IC7.4 | 133.34,14.44 151.76,14.44 151.76,48.73 149.22,51.27 SKT.22 | R7.2 133.34,14.44
N$28
  Bottom 0.305: IC9.19 109.85,11.9 106.67,8.73 102.86,8.73 100.96,6.82 100.96,4.28 141.6,4.28 142.87,5.55 IC7.8
N$29
  Bottom 0.305: IC7.6 137.79,8.09 140.33,10.63 IC7.10
N$30
  Top 0.305: 146.68,84.29 145.41,83.02 IC10.12 | 146.68,84.29 146.68,86.83 145.41,88.1 IC10.14 | 146.68,84.29 146.68,74.77 145.41,73.5 145.41,65.24 146.68,63.97 SKT.27
N$31
  Top 0.305: SKT.1 133.98,67.78 133.98,91.91 135.25,93.18 IC10.1
N$32  (via drill 0.8)
  Top 0.305: v126.36,63.34 126.36,69.05 120.01,75.4 IC11.13
  Bottom 0.305: v126.36,63.34 126.99,62.7 145.41,62.7 146.68,61.43 SKT.26
N$33
  Bottom 0.305: IC11.12 120.01,72.86 120.64,73.5 139.06,73.5 142.23,76.67 146.04,76.67 146.68,77.3 146.68,84.92 144.78,84.92 IC10.13
N$34
  Bottom 0.305: IC11.11 120.01,70.32 122.55,72.86 144.78,72.86 147.31,75.4 147.31,86.83 139.06,86.83 137.79,88.1 IC10.3
N$35
  Top 0.305: IC11.14 120.01,77.94 128.27,69.69 128.27,64.61 128.9,63.97 SKT.2
N$36  (via drill 0.8)
  Top 0.305: v139.06,76.67 140.97,74.77 140.97,59.52 146.68,53.81 SKT.23
  Bottom 0.305: v139.06,76.67 123.82,76.67 120.01,80.48 IC11.15
N$37
  Top 0.305: SKT.21 146.68,48.73 135.25,60.16 135.25,64.61 134.62,65.24 130.17,65.24 130.17,72.86 120.01,83.02 IC11.16
N$38
  Top 0.305: IC11.17 117.47,85.56 116.2,84.29 116.2,69.69 130.81,55.08 138.42,55.08 146.04,47.46 150.49,47.46 150.49,55.08 149.22,56.35 SKT.24
N$39
  Bottom 0.305: IC11.18 120.01,88.1 121.28,89.37 146.04,89.37 150.49,84.92 150.49,59.52 148.59,59.52 SKT.25
N$40
  Top 0.305: Q1.2 R1.2
N$41
  Bottom 0.305: T1.3 R4.1 56.51,10.63 R1.1
PCCTS
  Bottom 0.305: IC4.18 36.19,22.06 32.38,18.25 10.79,18.25 9.52,19.52 6.34,19.52 3.17,22.7 3.17,29.68 6.34,29.68 CN1.8
PCRTS
  Bottom 0.305: IC4.19 36.19,24.6 34.92,23.33 12.7,23.33 10.79,21.42 6.98,21.42 5.08,23.33 5.08,26.5 6.34,26.5 CN1.7
PCRXD  (via drill 0.8)
  Top 0.305: v20.31,25.23 28.57,16.98 IC4.5
  Bottom 0.305: v20.31,25.23 10.16,25.23 CN1.2
PCTXD
  Bottom 0.305: IC4.4 28.57,19.52 27.3,20.79 6.34,20.79 4.44,22.7 4.44,28.41 CN1.3
RESET
  Bottom 0.305: RESETS.1 R3.2
RST
  Top 0.305: R2.1 43.81,15.08 40.64,18.25 40.64,30.95 33.65,37.94 33.65,75.4 27.3,81.75 IC2.2
RTS
  Top 0.305: IC4.1 28.57,28.41 28.57,42.38 27.3,43.65 IC2.17
RXD  (via drill 0.8)
  Top 0.305: v32.38,53.17 32.38,23.33 31.11,22.06 IC4.3
  Bottom 0.305: v32.38,53.17 36.83,48.73 IC2.26
SELA  (via drill 0.8)
  Top 0.305: v62.86,46.19 68.57,51.91 v68.57,73.5
  Bottom 0.305: v62.86,46.19 45.08,46.19 42.54,43.65 IC2.24 | v68.57,73.5 94.61,73.5 95.24,74.13 138.42,74.13 142.23,77.94 IC10.10
SELB
  Top 0.305: IC2.23 42.54,41.11 43.81,42.38 43.81,72.22 43.18,72.86 38.1,72.86 36.83,74.13 36.83,84.92 45.08,93.18 105.41,93.18 107.94,95.72 141.6,95.72 141.6,76.67 142.87,75.4 IC10.9
SYNC  (via drill 0.8)
  Top 0.305: CHAIN.4 5.08,56.35 6.98,58.25 6.98,62.7 10.79,66.51 v14.6,66.51 | v17.77,66.51 v22.22,66.51
  Bottom 0.305: v22.22,66.51 24.76,63.97 IC2.9 | v14.6,66.51 v17.77,66.51
TGTVCC  (via drill 0.8)
  Top 0.305: R7.1 128.9,20.79 R6.1 121.91,25.23 121.91,33.49 | 121.91,33.49 121.91,60.8 120.01,62.7 IC12.20 | IC10.16 145.41,93.18 147.31,91.28 147.31,67.14 SKT.28 | v122.55,33.49 121.91,33.49
  Bottom 0.305: Q1.1 105.41,5.55 109.21,9.36 IC9.20 111.75,10 114.3,10 114.3,33.49 | 114.3,33.49 112.39,35.39 C7.1 | IC11.20 120.01,93.18 121.28,94.45 141.6,94.45 142.87,93.18 IC10.16 | IC12.20 120.01,62.7 122.55,65.24 145.41,65.24 146.68,66.51 SKT.28 147.95,67.14 143.5,71.59 139.69,71.59 138.42,70.32 C8.1 | 114.3,33.49 v122.55,33.49
TXD
  Bottom 0.305: IC4.2 28.57,24.6 22.22,30.95 22.22,44.92 38.73,44.92 40,46.19 IC2.25
VCC  (via drill 0.8)
  Top 0.305: IC1.30 93.34,63.97 94.61,65.24 94.61,67.78 93.34,69.05 IC1.32 v92.07,76.67 | R9.2 102.23,59.52 97.15,64.61 R8.2 | v135.88,36.03 135.88,29.04 IC7.14 | 16.5,64.61 16.5,23.96 28.57,11.9 IC4.7 | 16.5,64.61 16.5,71.59 | 16.5,71.59 R10.2 | 16.5,71.59 R5.1 | v9.52,62.7 10.79,62.7 12.7,64.61 16.5,64.61
  Bottom 0.305: R8.2 96.52,71.59 93.97,69.05 IC1.32 80,69.05 78.73,67.78 C5.1 60.96,67.78 59.69,69.05 44.45,69.05 43.18,67.78 36.19,67.78 | v135.88,36.03 134.62,37.3 118.1,37.3 114.3,41.11 114.3,58.89 R9.2 | v92.07,76.67 C4.1 | 22.86,88.1 29.84,88.1 31.11,89.37 DBUG.4 | 22.86,88.1 21.58,89.37 C6.+ 17.77,89.37 16.5,90.64 C3.1 15.87,90 6.98,81.11 6.34,81.11 POWER.1 6.34,79.84 14.6,71.59 R5.1 | 22.86,88.1 28.57,93.81 34.92,93.81 35.55,93.18 60.32,93.18 61.59,94.45 IC3.20 | 19.68,67.78 19.68,63.97 24.76,58.89 IC2.11 | R10.2 19.68,67.78 | 36.19,67.78 40,63.97 IC2.32 | 19.68,67.78 36.19,67.78 | v9.52,62.7 MODE.3

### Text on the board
Top: EPROM EMULATOR REV 1.0C | (C) 2005 P. A. Pemberton | philpem@philpem.me.uk | TOP COPPER
Bottom: EPROM EMULATOR REV 1.0C | (C) 2005 P. A. Pemberton | philpem@philpem.me.uk | BOTTOM COPPER
tPlace: S/N: | +5V | 0V | EPROM EMULATOR REV 1.0C | (C) 2005 P. A. Pemberton | philpem@philpem.me.uk | /RESET | RESET | TOP COMPONENT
